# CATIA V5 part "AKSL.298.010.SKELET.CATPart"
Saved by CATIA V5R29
Part number: АКСЛ.298.010.SKELET
Publications: "S металла", "основаниеProfile.1", "Уголок rofile.2", "ПЛТ симметрии OutputPlane.1 (Line.13)", "R гиба", "K-factor", "Уголок 2 Profile.3", "Plane.1"
Bounding box of the stored display mesh (mm): x -75 to 75, y -75 to 75, z 0 to 0
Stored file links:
  Z:\ООО Аксель\Соединения бруса\Соединения бруса\Соединения из листа\АКСЛ.298.010 (Основание)\AKSL.298.010.SKELET.CATPart
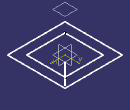
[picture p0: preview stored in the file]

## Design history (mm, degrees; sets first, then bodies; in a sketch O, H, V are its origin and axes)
Parameters
  `S металла` = 2 mm
  `R гиба` = 1.9 mm
  `K-factor` = 0.49
Set1
  Plane1: type Offset, RefPlane xy-plane, Offset 103
Body1 (main body)
  Sketch1 on xy-plane, origin (0, 0, 0), H (1, 0, 0), V (0, 1, 0)
    line L1 (75, 75) -> (75, -75)
    line L2 (75, -75) -> (-75, -75)
    line L3 (-75, -75) -> (-75, 75)
    line L4 (-75, 75) -> (75, 75)
    point P5 (0, 52)
    construction line L5 (50, 52) -> (-52, 52)
    construction line L6 (-52, 52) -> (-52, -52)
    line L7 (-50, -52) -> (-50, 50)
    line L8 (-50, 50) -> (50, 50)
    point P8 (0, 50)
    construction line L9 (0, 50) -> (0, 52)
    construction line L10 (-75, 0) -> (75, 0)
    point P9 (-75, 0)
    point P10 (75, 0)
    construction line L11 (0, 75) -> (0, -75)
    point P11 (0, 75)
    point P12 (0, -75)
    construction line L12 (0, 0) -> (84.5, 84.5)
    point P14 (52, 0)
    point P15 (50, 0)
    construction line L13 (50, 0) -> (52, 0)
    point P16 (50, 50)
    line L14 (50, 50) -> (50, -50)
    line L15 (50, -50) -> (-50, -50)
    construction line L16 (-50, -50) -> (-50, 50)
    construction line L17 (-50, 50) -> (50, 50)
    line L18 (50, 50) -> (50, 52)
    construction line L19 (-50, -52) -> (-52, -52)
    curve C1
    curve C2
    curve C3
    curve C4
    distance L3 L1 = 150
    distance L4 L2 = 150
    distance L7 L11 = 50
    distance L8 L10 = 50
    distance L7 L6 = 2 {= `S металла`}
    distance L5 L8 = 2 {= `S металла`}
    angle L12 L10 = 45
    distance L16 L14 = 100
    distance L17 L15 = 100
    distance L15 L19 = 2 {= `S металла`}
    vertical: L1 V, L3 V, L6 V, L7 V, L9 V, L11 V, L14 V, L16 V, L18 V
    horizontal: L2 H, L4 H, L5 H, L8 H, L10 H, L15 H, L17 H, L19 H
    equidistance: L1 L3 O, L2 L4 O, L14 L16 O, L15 L17 O
    coincidence: P5 V, P8 V, P8 L8, P16 L14, P5 L5
    midpoint: P9 L3, P10 L1, P11 L4, P12 L2
    symmetry: P5 P14 L12, P8 P15 L12, L9 L13 L12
